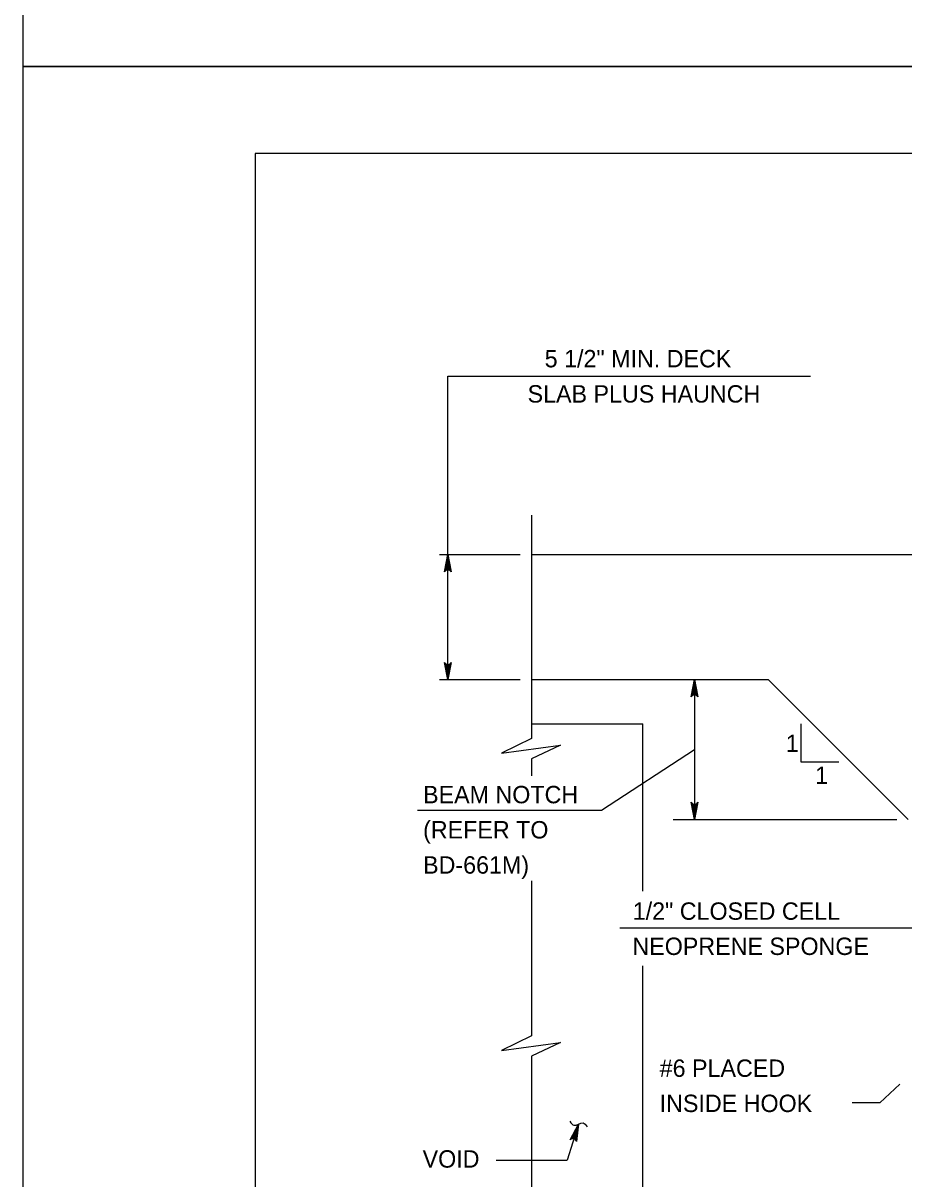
# Model space of a CAD drawing. Extents: x 636530 to 644067, y 294168 to 299122.
# Drawn here: x 638165.8 to 638317.7, y 295758.6 to 295958 of the extents above; entities that cross this region are included whole.
import ezdxf

# ---------------------------------------------------------------- set-up
doc = ezdxf.new("R2010")
doc.units = 0
doc.layers.add('1', color=7, linetype='Continuous')
doc.layers.add('PLT-BNDY', color=7, linetype='Continuous')

msp = doc.modelspace()

# ---------------------------------------------------------------- linework, layer by layer
at = {"layer": '1'}
for p, q in [((638991.78, 295935.48), (638205.78, 295935.48)), ((638205.78, 295935.48), (638205.78, 295371.48)), ((638239.03, 295844.71), (638239.03, 295897.06)), ((638239.03, 295897.06), (638301.56, 295897.06)), ((638253.46, 295873.11), (638253.46, 295834.55)), ((638237.57, 295866.3), (638251.52, 295866.3)), ((638253.46, 295866.3), (638357.85, 295866.3)), ((638237.57, 295844.71), (638251.52, 295844.71)), ((638253.46, 295844.71), (638294.26, 295844.71)), ((638281.57, 295844.71), (638281.57, 295820.58)), ((638318.39, 295820.58), (638294.26, 295844.71)), ((638253.46, 295837.09), (638272.67, 295837.09)), ((638272.67, 295808.24), (638272.67, 295837.09)), ((638299.88, 295837.11), (638299.88, 295830.52)), ((638265.55, 295822.19), (638281.57, 295832.68)), ((638253.46, 295831.03), (638253.46, 295828.13)), ((638299.88, 295830.52), (638306.47, 295830.52)), ((638233.81, 295822.19), (638265.55, 295822.19)), ((638277.87, 295820.58), (638316.48, 295820.58)), ((638253.46, 295810.02), (638253.46, 295783.27)), ((638268.69, 295801.92), (638326.37, 295801.92)), ((638272.67, 295706.28), (638272.67, 295795.36)), ((638253.46, 295779.75), (638253.46, 295733.21)), ((638261.55, 295768.02), (638259.63, 295761.81)), ((638247.37, 295761.81), (638259.63, 295761.81))]:
    msp.add_line(p, q, dxfattribs=at)
for points in [[(638239.03, 295866.3), (638239.59, 295863.31), (638239.51, 295863.43), (638239.43, 295863.54), (638239.33, 295863.6), (638239.23, 295863.66), (638239.13, 295863.68), (638239.03, 295863.7), (638238.93, 295863.68), (638238.83, 295863.66), (638238.73, 295863.6), (638238.63, 295863.54), (638238.55, 295863.43), (638238.47, 295863.31), (638239.03, 295866.3), (638238.55, 295863.43), (638238.63, 295863.54), (638239.03, 295866.3), (638238.73, 295863.6), (638238.83, 295863.66), (638239.03, 295866.3), (638238.93, 295863.68), (638239.03, 295863.7), (638239.03, 295866.3), (638239.13, 295863.68), (638239.23, 295863.66), (638239.03, 295866.3), (638239.33, 295863.6), (638239.43, 295863.54), (638239.03, 295866.3), (638239.51, 295863.43)], [(638239.03, 295844.71), (638238.47, 295847.69), (638238.55, 295847.58), (638238.63, 295847.46), (638238.73, 295847.4), (638238.83, 295847.34), (638238.93, 295847.33), (638239.03, 295847.31), (638239.13, 295847.33), (638239.23, 295847.34), (638239.33, 295847.4), (638239.43, 295847.46), (638239.51, 295847.58), (638239.59, 295847.69), (638239.03, 295844.71), (638239.51, 295847.58), (638239.43, 295847.46), (638239.03, 295844.71), (638239.33, 295847.4), (638239.23, 295847.34), (638239.03, 295844.71), (638239.13, 295847.33), (638239.03, 295847.31), (638239.03, 295844.71), (638238.93, 295847.33), (638238.83, 295847.34), (638239.03, 295844.71), (638238.73, 295847.4), (638238.63, 295847.46), (638239.03, 295844.71), (638238.55, 295847.58)], [(638281.57, 295844.71), (638282.13, 295841.73), (638282.05, 295841.84), (638281.97, 295841.96), (638281.87, 295842.01), (638281.77, 295842.07), (638281.67, 295842.09), (638281.57, 295842.11), (638281.47, 295842.09), (638281.37, 295842.07), (638281.27, 295842.01), (638281.17, 295841.96), (638281.09, 295841.84), (638281.01, 295841.73), (638281.57, 295844.71), (638281.09, 295841.84), (638281.17, 295841.96), (638281.57, 295844.71), (638281.27, 295842.01), (638281.37, 295842.07), (638281.57, 295844.71), (638281.47, 295842.09), (638281.57, 295842.11), (638281.57, 295844.71), (638281.67, 295842.09), (638281.77, 295842.07), (638281.57, 295844.71), (638281.87, 295842.01), (638281.97, 295841.96), (638281.57, 295844.71), (638282.05, 295841.84)], [(638253.46, 295834.55), (638248.28, 295832.01), (638258.43, 295833.39), (638253.46, 295831.03)], [(638281.57, 295820.58), (638281.01, 295823.56), (638281.09, 295823.45), (638281.17, 295823.33), (638281.27, 295823.27), (638281.37, 295823.21), (638281.47, 295823.19), (638281.57, 295823.18), (638281.67, 295823.19), (638281.77, 295823.21), (638281.87, 295823.27), (638281.97, 295823.33), (638282.05, 295823.45), (638282.13, 295823.56), (638281.57, 295820.58), (638282.05, 295823.45), (638281.97, 295823.33), (638281.57, 295820.58), (638281.87, 295823.27), (638281.77, 295823.21), (638281.57, 295820.58), (638281.67, 295823.19), (638281.57, 295823.18), (638281.57, 295820.58), (638281.47, 295823.19), (638281.37, 295823.21), (638281.57, 295820.58), (638281.27, 295823.27), (638281.17, 295823.33), (638281.57, 295820.58), (638281.09, 295823.45)], [(638253.46, 295783.27), (638248.28, 295780.73), (638258.43, 295782.11), (638253.46, 295779.75)], [(638316.96, 295774.94), (638313.5, 295771.71), (638308.78, 295771.71)], [(638261.55, 295768.02), (638261.2, 295765.01), (638261.12, 295765.27), (638260.96, 295765.45), (638260.78, 295765.54), (638260.58, 295765.56), (638260.35, 295765.51), (638260.13, 295765.34), (638261.55, 295768.02), (638260.35, 295765.51), (638260.58, 295765.56), (638261.55, 295768.02), (638260.78, 295765.54), (638260.96, 295765.45), (638261.55, 295768.02), (638261.12, 295765.27)]]:
    msp.add_lwpolyline(points, dxfattribs=at)
msp.add_spline([(638260.07, 295768.51), (638260.76, 295767.82), (638262.35, 295768.23), (638263.04, 295767.58)], degree=3, dxfattribs=at)
at = {"layer": 'PLT-BNDY'}
for points in [[(638165.78, 296544.48), (639006.78, 296544.48), (639006.78, 295950.48), (638165.78, 295950.48)], [(638165.78, 295950.48), (639006.78, 295950.48), (639006.78, 295356.48), (638165.78, 295356.48)]]:
    msp.add_lwpolyline(points, close=True, dxfattribs=at)

# ---------------------------------------------------------------- texts
at = {"layer": '1'}
for s, p in [('5 1/2" MIN. DECK', (638255.73, 295898.59)), ('SLAB PLUS HAUNCH', (638252.78, 295892.51))]:
    msp.add_text(s, height=3, dxfattribs=at).set_placement(p)
for s, p in [('1', (638297.32, 295832.23)), ('1', (638302.38, 295826.72)), ('BEAM NOTCH', (638234.76, 295823.38)), ('(REFER TO', (638234.76, 295817.31)), ('BD-661M)', (638234.76, 295811.24)), ('1/2" CLOSED CELL', (638270.91, 295803.28)), ('NEOPRENE SPONGE', (638270.86, 295797.21)), ('#6 PLACED ', (638275.56, 295776.18)), ('INSIDE HOOK', (638275.56, 295770.11)), ('VOID', (638234.68, 295760.52))]:
    msp.add_text(s, height=3, rotation=360, dxfattribs=at).set_placement(p)

doc.saveas('drawing.dxf')
